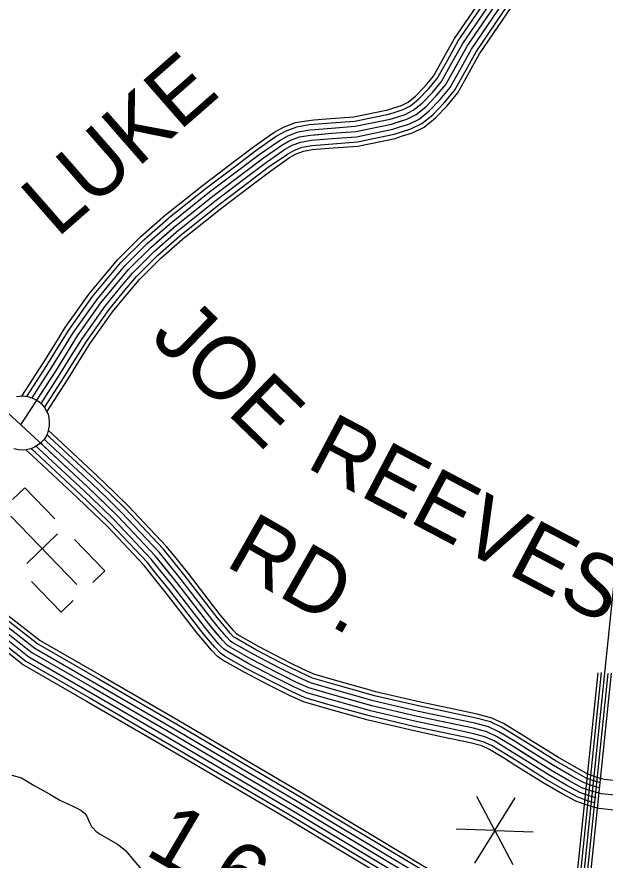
# Model space of a CAD drawing. Extents: x 1551132 to 1791609, y 378168 to 563823.
# Drawn here: x 1703654 to 1707137, y 427562 to 432556 of the extents above; entities that cross this region are included whole.
import ezdxf

# ---------------------------------------------------------------- set-up
doc = ezdxf.new("R2010")
doc.units = 0
for name, color, linetype in [('DESIGN - ROW - Right-of-Way and Easement Labels', 7, 'Continuous'), ('DESIGN - TRAFFIC CONTROL PERMANENT - Signalization', 7, 'Continuous'), ('DESIGN - TRANSPORTATION - Text', 7, 'Continuous'), ('DESIGN - UTILITIES - Cable (Underground) with Text', 7, 'Continuous'), ('SURVEY - CENTERLINE - Preliminary Text', 7, 'Continuous'), ('SURVEY - DRAINAGE - Natural Features', 7, 'Continuous'), ('SURVEY - TRANSPORTATION - Roads', 7, 'Continuous'), ('SURVEY - VEGETATION - Features with Text', 7, 'Continuous')]:
    doc.layers.add(name, color=color, linetype=linetype)

msp = doc.modelspace()

# ---------------------------------------------------------------- linework, layer by layer
at = {"layer": 'DESIGN - TRAFFIC CONTROL PERMANENT - Signalization'}
for q in [(1706376.357, 427939.716), (1706604.323, 427931.755), (1706255.495, 427746.288), (1706362.55, 427544.899), (1706590.517, 427536.946), (1706711.378, 427730.366)]:
    msp.add_line((1706483.462, 427738.327), q, dxfattribs=at)
at = {"layer": 'DESIGN - TRANSPORTATION - Text'}
msp.add_lwpolyline([(1703623.646, 428065.801), (1703681.469, 428049.1), (1703756.984, 428004.149), (1703848.424, 427953.006), (1703908.022, 427916.264), (1703985.645, 427881.305), (1704029.419, 427860.762), (1704041.327, 427852.612), (1704057.177, 427838.403), (1704068.993, 427822.245), (1704084.568, 427784.019), (1704096.326, 427761.851), (1704104.234, 427753.751), (1704122.017, 427733.517), (1704143.833, 427717.242), (1704199.499, 427686.541), (1704249.164, 427655.924), (1704274.963, 427637.598), (1704298.746, 427617.289), (1704344.145, 427562.688), (1704419.185, 427475.702)], dxfattribs=at)
at = {"layer": 'DESIGN - UTILITIES - Cable (Underground) with Text'}
for p, q in [((1703700.78, 429767.058), (1703629.062, 429697.797)), ((1703879.036, 429582.255), (1703700.697, 429767.016)), ((1703894.738, 429494.028), (1703712.268, 429317.805)), ((1704175.338, 429275.567), (1703995.99, 429461.162)), ((1704175.205, 429275.484), (1704103.662, 429206.306)), ((1703741.578, 429211.72), (1703916.351, 429030.834)), ((1703916.443, 429030.967), (1703987.144, 429099.211))]:
    msp.add_line(p, q, dxfattribs=at)
msp.add_lwpolyline([(1703618.588, 429599.503), (1704009.76, 429194.514)], dxfattribs=at)
at = {"layer": 'SURVEY - CENTERLINE - Preliminary Text'}
for points in [[(1701209.763, 432652.228), (1701359.142, 432553.751), (1701538.755, 432418.539), (1701759.974, 432215.675), (1701910.154, 432034.471), (1702098.975, 431751.98), (1702303.228, 431418.996), (1702465.316, 431131.347), (1702571.305, 430911.817), (1702659.186, 430687.844), (1702742.334, 430398.612), (1702844.765, 430049.611), (1702965.145, 429690.66), (1703047.685, 429445.92), (1703104.967, 429331.659), (1703251.713, 429128.287), (1703332.061, 429031.801), (1703487.766, 428880.23), (1703693.511, 428717.901), (1704065.744, 428504.096), (1704501.958, 428251.081), (1705242.932, 427815.937), (1705944.374, 427394.851), (1706600.392, 427005.216)], [(1701445.449, 432676.179), (1701634.594, 432533.792), (1701868.705, 432319.103), (1702030.343, 432124.082), (1702225.063, 431832.757), (1702432.292, 431494.924), (1702598.071, 431200.716), (1702708.602, 430971.802), (1702801.124, 430735.979), (1702886.106, 430440.379), (1702987.611, 430094.512), (1703107.05, 429738.394), (1703186.206, 429503.68), (1703233.414, 429409.519), (1703370.077, 429220.106), (1703442.092, 429133.629), (1703586.613, 428992.95), (1703777.609, 428842.255), (1704140.584, 428633.766), (1704577.423, 428380.393), (1705319.364, 427944.673), (1706021.122, 427523.404), (1706676.84, 427133.944)], [(1701459.698, 432696.388), (1701650.41, 432552.818), (1701886.663, 432336.179), (1702050.184, 432138.874), (1702245.88, 431846.091), (1702453.599, 431507.457), (1702619.995, 431212.166), (1702731.268, 430981.702), (1702824.557, 430743.921), (1702909.838, 430447.271), (1703011.194, 430101.929), (1703130.474, 429746.27), (1703209.073, 429513.214), (1703254.621, 429422.37), (1703389.618, 429235.265), (1703460.258, 429150.438), (1703602.93, 429011.559), (1703791.492, 428862.788), (1704152.942, 428655.175), (1704589.881, 428401.735), (1705331.989, 427965.932), (1706033.797, 427544.63), (1706689.465, 427155.195)], [(1701409.708, 432625.478), (1701594.903, 432486.066), (1701823.681, 432276.269), (1701980.569, 432086.972), (1702172.848, 431799.306), (1702378.843, 431463.481), (1702543.097, 431171.99), (1702651.745, 430946.959), (1702742.342, 430716.045), (1702826.565, 430423.079), (1702928.454, 430075.92), (1703048.285, 429718.627), (1703128.841, 429479.763), (1703180.223, 429377.277), (1703321.061, 429182.08), (1703396.526, 429091.461), (1703545.681, 428946.274), (1703742.785, 428790.762), (1704109.593, 428580.065), (1704546.174, 428326.841), (1705287.715, 427891.364), (1705989.34, 427470.17), (1706645.183, 427080.635)], [(1701409.708, 432625.478), (1701594.903, 432486.066), (1701823.681, 432276.269), (1701980.569, 432086.972), (1702172.848, 431799.306), (1702378.843, 431463.481), (1702543.097, 431171.99), (1702651.745, 430946.959), (1702742.342, 430716.045), (1702826.565, 430423.079), (1702928.454, 430075.92), (1703048.285, 429718.627), (1703128.841, 429479.763), (1703180.223, 429377.277), (1703321.061, 429182.08), (1703396.526, 429091.461), (1703545.681, 428946.274), (1703742.785, 428790.762), (1704109.593, 428580.065), (1704546.174, 428326.841), (1705287.715, 427891.364), (1705989.34, 427470.17), (1706645.183, 427080.635)], [(1701427.574, 432650.828), (1701614.745, 432509.933), (1701846.197, 432297.686), (1702005.452, 432105.523), (1702198.956, 431816.032), (1702405.567, 431479.198), (1702570.588, 431186.357), (1702680.169, 430959.376), (1702771.733, 430726.012), (1702856.331, 430431.729), (1702958.029, 430085.22), (1703077.667, 429728.511), (1703157.524, 429491.721), (1703206.823, 429393.394), (1703345.569, 429201.089), (1703419.309, 429112.545), (1703566.147, 428969.616), (1703760.201, 428816.512), (1704125.092, 428606.915), (1704561.799, 428353.617), (1705303.539, 427918.023), (1706005.231, 427496.787), (1706661.016, 427107.285)], [(1701373.967, 432574.776), (1701555.213, 432438.34), (1701778.657, 432233.434), (1701930.795, 432049.863), (1702120.632, 431765.856), (1702325.394, 431432.039), (1702488.124, 431143.264), (1702594.888, 430922.117), (1702683.56, 430696.111), (1702767.025, 430405.778), (1702869.297, 430057.328), (1702989.519, 429698.86), (1703071.476, 429455.845), (1703127.033, 429345.034), (1703272.046, 429144.054), (1703350.961, 429049.293), (1703504.749, 428899.598), (1703707.961, 428739.269), (1704078.602, 428526.363), (1704514.925, 428273.29), (1705256.065, 427838.054), (1705957.557, 427416.935), (1706613.525, 427027.325)], [(1701391.842, 432600.127), (1701575.062, 432462.199), (1701801.165, 432254.852), (1701955.686, 432068.422), (1702146.74, 431782.581), (1702352.119, 431447.764), (1702515.606, 431157.623), (1702623.32, 430934.542), (1702712.951, 430706.078), (1702796.799, 430414.429), (1702898.88, 430066.62), (1703018.902, 429708.744), (1703100.158, 429467.804), (1703153.624, 429361.16), (1703296.554, 429163.071), (1703373.743, 429070.377), (1703525.215, 428922.932), (1703725.368, 428765.011), (1704094.093, 428553.214), (1704530.549, 428300.066), (1705271.89, 427864.705), (1705973.448, 427443.552), (1706629.35, 427053.984)]]:
    msp.add_lwpolyline(points, dxfattribs=at)
at = {"layer": 'SURVEY - DRAINAGE - Natural Features'}
for points in [[(1706251.033, 425895.095), (1706290.29, 426025.382), (1706314.398, 426110.784), (1706268.483, 426269.955), (1706539.46, 426249.146), (1706671.282, 427285.932), (1706990.5, 427277.907), (1707208.862, 429376.628), (1707434.457, 429376.962), (1707947.338, 433586.489)], [(1706251.033, 425895.095), (1706290.29, 426025.382), (1706314.398, 426110.784), (1706268.483, 426269.955), (1706539.46, 426249.146), (1706671.282, 427285.932), (1706990.5, 427277.907), (1707208.862, 429376.628), (1707434.457, 429376.962), (1707947.338, 433586.489)], [(1706954.542, 427318.824), (1707095.231, 428671.027)], [(1706972.517, 427298.366), (1707115.522, 428672.802)], [(1706990.5, 427277.907), (1707135.305, 428669.685)], [(1707008.474, 427257.464), (1707155.08, 428666.485)], [(1707025.557, 427238.006), (1707174.471, 428669.235)]]:
    msp.add_lwpolyline(points, dxfattribs=at)
at = {"layer": 'SURVEY - TRANSPORTATION - Roads'}
for points in [[(1706182.354, 432314.622), (1706245.303, 432427.608), (1706436.032, 432708.432), (1706457.048, 432740.1)], [(1706204.82, 432302.105), (1706267.219, 432414.099), (1706457.381, 432694.098), (1706478.472, 432725.883)], [(1706231.895, 432287.021), (1706293.627, 432397.816), (1706483.114, 432676.823), (1706504.297, 432708.741)], [(1703678.062, 430138.93), (1703883.84, 430458.214), (1704013.954, 430666.853), (1704151.909, 430861.391), (1704315.881, 431059.638), (1704447.153, 431190.216), (1704598.424, 431322.57), (1704814.052, 431494.208), (1705106.129, 431715.006), (1705222.876, 431795.716), (1705271.125, 431823.183), (1705327.299, 431844.551), (1705393.347, 431855.801), (1705519.328, 431866.368), (1705661.291, 431876.752), (1705871.536, 431920.378), (1705963.751, 431949.345), (1706017.991, 431976.738), (1706074.423, 432022.122), (1706137.063, 432087.441), (1706193.729, 432154.834), (1706320.043, 432381.532), (1706508.855, 432659.539)], [(1706258.977, 432271.929), (1706320.043, 432381.532), (1706508.855, 432659.539), (1706530.129, 432691.598)], [(1706286.06, 432256.837), (1706346.459, 432365.248), (1706534.596, 432642.255), (1706555.962, 432674.456)], [(1706313.134, 432241.753), (1706372.866, 432348.964), (1706560.329, 432624.98), (1706581.787, 432657.314)], [(1706334.726, 432229.72), (1706393.924, 432335.981), (1706580.853, 432611.205), (1706602.378, 432643.647)], [(1705885.753, 432016.789), (1705930.618, 432030.881), (1705970.217, 432050.881), (1706015.041, 432086.932), (1706071.773, 432146.092), (1706121.189, 432204.86), (1706182.362, 432314.647)], [(1705893.461, 431992.255), (1705940.335, 432006.98), (1705984.217, 432029.139), (1706032.449, 432067.932), (1706090.915, 432128.892), (1706142.455, 432190.193), (1706204.829, 432302.13)], [(1705902.744, 431962.679), (1705952.043, 431978.163), (1706001.108, 432002.938), (1706053.432, 432045.023), (1706113.989, 432108.166), (1706168.096, 432172.518), (1706231.903, 432287.038)], [(1705912.035, 431933.103), (1705963.751, 431949.345), (1706017.991, 431976.738), (1706074.423, 432022.122), (1706137.063, 432087.441), (1706193.729, 432154.834), (1706258.986, 432271.946)], [(1705921.327, 431903.527), (1705975.459, 431920.528), (1706034.874, 431950.537), (1706095.414, 431999.222), (1706160.138, 432066.715), (1706219.362, 432137.15), (1706286.068, 432256.854)], [(1705930.61, 431873.952), (1705987.167, 431891.711), (1706051.765, 431924.336), (1706116.397, 431976.313), (1706183.212, 432045.99), (1706245.003, 432119.475), (1706313.143, 432241.762)], [(1705938.018, 431850.368), (1705996.5, 431868.735), (1706065.223, 431903.444), (1706133.13, 431958.054), (1706201.612, 432029.464), (1706265.435, 432105.375), (1706334.734, 432229.736)], [(1705411.889, 431945.378), (1705512.461, 431953.82), (1705649.133, 431963.812), (1705849.428, 432005.38), (1705885.769, 432016.789)], [(1705414.039, 431919.753), (1705514.478, 431928.178), (1705652.691, 431938.287), (1705855.912, 431980.454), (1705893.477, 431992.255)], [(1705416.63, 431888.86), (1705516.903, 431897.277), (1705656.991, 431907.519), (1705863.72, 431950.42), (1705902.761, 431962.679)], [(1704934.016, 431694.855), (1705054.722, 431786.107), (1705176.153, 431870.051), (1705233.618, 431902.769), (1705304.125, 431929.586), (1705382.289, 431942.903), (1705411.897, 431945.387)], [(1704949.524, 431674.338), (1705069.788, 431765.257), (1705189.852, 431848.259), (1705244.609, 431879.435), (1705310.916, 431904.652), (1705385.531, 431917.361), (1705414.047, 431919.761)], [(1705419.222, 431857.968), (1705519.328, 431866.368), (1705661.291, 431876.752), (1705871.536, 431920.378), (1705912.052, 431933.103)], [(1705421.813, 431827.075), (1705521.753, 431835.459), (1705665.591, 431845.984), (1705879.353, 431890.335), (1705921.343, 431903.527)], [(1704968.216, 431649.612), (1705087.963, 431740.131), (1705206.36, 431821.983), (1705257.867, 431851.309), (1705319.107, 431874.601), (1705389.439, 431886.585), (1705416.647, 431888.869)], [(1704986.907, 431624.878), (1705106.129, 431715.006), (1705222.876, 431795.716), (1705271.125, 431823.183), (1705327.299, 431844.551), (1705393.347, 431855.801), (1705419.238, 431857.976)], [(1705424.405, 431796.183), (1705524.178, 431804.558), (1705669.891, 431815.217), (1705887.161, 431860.301), (1705930.626, 431873.952)], [(1705005.598, 431600.144), (1705124.295, 431689.88), (1705239.393, 431769.449), (1705284.383, 431795.058), (1705335.49, 431814.5), (1705397.256, 431825.017), (1705421.83, 431827.084)], [(1705426.472, 431771.549), (1705526.119, 431779.916), (1705673.316, 431790.683), (1705893.394, 431836.351), (1705938.035, 431850.368)], [(1705024.289, 431575.418), (1705142.47, 431664.754), (1705255.901, 431743.173), (1705297.641, 431766.932), (1705343.682, 431784.449), (1705401.164, 431794.241), (1705424.43, 431796.191)], [(1705039.197, 431555.701), (1705156.953, 431644.72), (1705269.067, 431722.231), (1705308.208, 431744.506), (1705350.207, 431760.482), (1705404.28, 431769.699), (1705426.497, 431771.565)], [(1704534.876, 431383.522), (1704542.2, 431389.93), (1704760.287, 431563.526), (1704934.025, 431694.863)], [(1704551.809, 431364.171), (1704558.683, 431370.18), (1704776.045, 431543.201), (1704949.533, 431674.346)], [(1704572.225, 431340.837), (1704578.558, 431346.379), (1704795.053, 431518.709), (1704968.224, 431649.62)], [(1704592.633, 431317.503), (1704598.424, 431322.57), (1704814.052, 431494.208), (1704986.915, 431624.886)], [(1704613.04, 431294.169), (1704618.29, 431298.761), (1704833.052, 431469.707), (1705005.606, 431600.152)], [(1704633.457, 431270.835), (1704638.165, 431274.96), (1704852.06, 431445.215), (1705024.298, 431575.427)], [(1704649.731, 431252.235), (1704654.006, 431255.977), (1704867.21, 431425.681), (1705039.206, 431555.71)], [(1704170.834, 431021.904), (1704251.007, 431118.831), (1704387.287, 431254.385), (1704534.884, 431383.53)], [(1704190.65, 431005.512), (1704270.023, 431101.472), (1704404.837, 431235.576), (1704551.817, 431364.171)], [(1704214.541, 430985.753), (1704292.956, 431080.555), (1704425.995, 431212.892), (1704572.233, 431340.845)], [(1704238.424, 430965.994), (1704315.881, 431059.638), (1704447.153, 431190.216), (1704592.641, 431317.512)], [(1704262.307, 430946.235), (1704338.805, 431038.721), (1704468.31, 431167.541), (1704613.049, 431294.178)], [(1704286.198, 430926.476), (1704361.738, 431017.804), (1704489.468, 431144.857), (1704633.465, 431270.852)], [(1704305.239, 430910.717), (1704380.012, 431001.12), (1704506.335, 431126.773), (1704649.74, 431252.243)], [(1703872.982, 430606.568), (1703940.906, 430715.479), (1704082.244, 430914.792), (1704170.842, 431021.912)], [(1703894.799, 430592.959), (1703962.322, 430701.22), (1704102.669, 430899.134), (1704190.659, 431005.52)], [(1703921.106, 430576.558), (1703988.138, 430684.036), (1704127.285, 430880.267), (1704214.541, 430985.761)], [(1703947.406, 430560.15), (1704013.954, 430666.853), (1704151.909, 430861.391), (1704238.432, 430966.002)], [(1703973.705, 430543.741), (1704039.77, 430649.669), (1704176.534, 430842.516), (1704262.324, 430946.243)], [(1704000.013, 430527.341), (1704065.586, 430632.485), (1704201.15, 430823.648), (1704286.206, 430926.484)], [(1704020.979, 430514.257), (1704086.169, 430618.785), (1704220.783, 430808.598), (1704305.256, 430910.734)], [(1707254.994, 427940.158), (1707115.289, 427953.766), (1707057.532, 427970.433), (1706999.816, 427991.109), (1706924.335, 428031.993), (1706815.137, 428095.278), (1706586.926, 428237.973), (1706493.645, 428295.075), (1706435.996, 428321.75), (1706358.307, 428342.651), (1706025.414, 428412.503), (1705756.387, 428475.613), (1705525.334, 428540.289), (1705381.938, 428581.957), (1705306.39, 428616.841), (1705189.142, 428674.218), (1705042.138, 428751.944), (1704917.041, 428823.413), (1704899.191, 428835.63), (1704871.533, 428863.964), (1704790.669, 428960.942), (1704601.515, 429205.256), (1704473.376, 429364.81), (1704252.148, 429599.483), (1704074.202, 429771.621), (1703757.718, 430065.42), (1703099.001, 430673.311)], [(1703683.637, 430309.493), (1703809.759, 430505.19), (1703872.991, 430606.576)], [(1703713.244, 430307.968), (1703831.475, 430491.415), (1703894.807, 430592.967)], [(1703744.519, 430299.259), (1703857.658, 430474.814), (1703921.115, 430576.567)], [(1703772.235, 430285.042), (1703883.84, 430458.214), (1703947.414, 430560.158)], [(1703797.326, 430266.759), (1703910.023, 430441.613), (1703973.713, 430543.749)], [(1703818.525, 430242.416), (1703936.206, 430425.013), (1704000.021, 430527.349)], [(1703831.65, 430217.166), (1703957.08, 430411.779), (1704020.996, 430514.265)], [(1703865.082, 430084.071), (1703840.433, 430106.946)], [(1703848.266, 430065.962), (1703832.125, 430080.945)], [(1704213.724, 429722.92), (1704116.851, 429816.63), (1703848.258, 430065.97)], [(1704230.907, 429740.678), (1704133.851, 429834.572), (1703865.074, 430084.087)], [(1703784.993, 429997.802), (1703767.685, 430013.869)], [(1703806.084, 430020.519), (1703794.342, 430031.419)], [(1704170.617, 429678.352), (1704074.202, 429771.621), (1703806.075, 430020.527)], [(1703827.175, 430043.236), (1703815.634, 430053.953)], [(1704192.166, 429700.636), (1704095.527, 429794.121), (1703827.167, 430043.244)], [(1703746.41, 429956.234), (1703709.328, 429990.66)], [(1703763.901, 429975.076), (1703739.202, 429998.002)], [(1704109.635, 429615.3), (1704013.862, 429707.944), (1703746.402, 429956.234)], [(1704127.509, 429633.784), (1704031.553, 429726.611), (1703763.893, 429975.084)], [(1704149.067, 429656.068), (1704052.878, 429749.12), (1703784.984, 429997.81)], [(1704561.816, 429353.702), (1704520.175, 429405.553), (1704296.28, 429643.051), (1704213.716, 429722.928)], [(1704581.09, 429369.177), (1704538.833, 429421.795), (1704313.872, 429660.426), (1704230.899, 429740.687)], [(1704489.309, 429295.467), (1704449.977, 429344.443), (1704230.082, 429577.699), (1704149.059, 429656.076)], [(1704513.475, 429314.876), (1704473.376, 429364.81), (1704252.148, 429599.483), (1704170.608, 429678.36)], [(1704537.641, 429334.285), (1704496.776, 429385.178), (1704274.214, 429621.267), (1704192.158, 429700.644)], [(1704445.085, 429259.949), (1704407.161, 429307.167), (1704189.708, 429537.84), (1704109.626, 429615.308)], [(1704465.135, 429276.05), (1704426.577, 429324.068), (1704208.016, 429555.915), (1704127.501, 429633.792)], [(1704889.55, 428977.759), (1704858.275, 429015.276), (1704669.605, 429258.958), (1704581.074, 429369.194)], [(1704822.951, 428922.224), (1704790.669, 428960.942), (1704601.515, 429205.256), (1704513.467, 429314.892)], [(1704846.759, 428942.074), (1704814.835, 428980.367), (1704625.856, 429224.457), (1704537.633, 429334.301)], [(1704870.567, 428961.933), (1704839.001, 428999.784), (1704650.197, 429243.649), (1704561.807, 429353.718)], [(1704755.586, 428866.047), (1704722.287, 428905.982), (1704532.633, 429150.938), (1704445.077, 429259.966)], [(1704775.336, 428882.514), (1704742.336, 428922.099), (1704552.833, 429166.863), (1704465.126, 429276.066)], [(1704799.143, 428902.373), (1704766.502, 428941.516), (1704577.174, 429186.056), (1704489.301, 429295.483)], [(1705263.574, 428706.818), (1705217.267, 428729.486), (1705072.012, 428806.279), (1704949.981, 428875.998), (1704939.273, 428883.331), (1704917.599, 428905.54), (1704870.558, 428961.95)], [(1705274.44, 428729.019), (1705228.475, 428751.511), (1705083.92, 428827.946), (1704963.114, 428896.965), (1704955.248, 428902.348), (1704935.957, 428922.107), (1704889.541, 428977.775)], [(1705236.325, 428651.125), (1705189.142, 428674.218), (1705042.138, 428751.944), (1704917.041, 428823.413), (1704899.191, 428835.63), (1704871.533, 428863.964), (1704822.943, 428922.241)], [(1705249.949, 428678.968), (1705203.2, 428701.852), (1705057.071, 428779.112), (1704933.507, 428849.705), (1704919.232, 428859.481), (1704894.566, 428884.748), (1704846.751, 428942.091)], [(1705197.767, 428572.34), (1705149.352, 428596.032), (1704999.872, 428675.067), (1704870.442, 428749.011), (1704842.484, 428768.145), (1704806.368, 428805.146), (1704755.578, 428866.064)], [(1705209.075, 428595.432), (1705161.018, 428618.949), (1705012.263, 428697.61), (1704884.1, 428770.828), (1704859.109, 428787.929), (1704825.468, 428822.388), (1704775.327, 428882.531)], [(1705222.7, 428623.283), (1705175.084, 428646.583), (1705027.205, 428724.777), (1704900.574, 428797.121), (1704879.15, 428811.779), (1704848.5, 428843.18), (1704799.135, 428902.39)], [(1705724.463, 428548.939), (1705542.342, 428599.916), (1705403.704, 428640.2), (1705333.014, 428672.843), (1705263.566, 428706.827)], [(1705731.13, 428572.74), (1705549.117, 428623.683), (1705412.379, 428663.417), (1705343.63, 428695.16), (1705274.432, 428729.027)], [(1705716.113, 428519.08), (1705533.834, 428570.098), (1705392.821, 428611.074), (1705319.698, 428644.842), (1705249.941, 428678.976)], [(1705699.397, 428459.379), (1705516.835, 428510.48), (1705371.055, 428552.839), (1705293.082, 428588.84), (1705222.692, 428623.291)], [(1705707.755, 428489.23), (1705525.334, 428540.289), (1705381.938, 428581.957), (1705306.39, 428616.841), (1705236.316, 428651.134)], [(1705684.114, 428404.761), (1705501.277, 428455.937), (1705351.147, 428499.555), (1705268.724, 428537.614), (1705197.759, 428572.34)], [(1705691.047, 428429.52), (1705508.327, 428480.663), (1705360.172, 428523.714), (1705279.765, 428560.84), (1705209.067, 428595.44)], [(1706212.677, 428461.812), (1706044.222, 428497.163), (1705777.987, 428559.615), (1705731.113, 428572.74)], [(1706201.235, 428407.286), (1706032.139, 428442.77), (1705764.112, 428505.647), (1705716.097, 428519.08)], [(1706207.602, 428437.62), (1706038.864, 428473.029), (1705771.829, 428535.672), (1705724.446, 428548.939)], [(1706188.502, 428346.601), (1706018.69, 428382.235), (1705748.663, 428445.578), (1705699.38, 428459.379)], [(1706194.869, 428376.943), (1706025.414, 428412.503), (1705756.387, 428475.613), (1705707.739, 428489.23)], [(1706700.415, 428269.283), (1706632.55, 428311.717), (1706534.627, 428371.66), (1706465.679, 428403.569), (1706378.489, 428427.02), (1706212.66, 428461.821)], [(1706182.136, 428316.267), (1706011.965, 428351.976), (1705740.946, 428415.553), (1705691.031, 428429.52)], [(1706670.874, 428222.04), (1706603.234, 428264.341), (1706508.295, 428322.451), (1706446.604, 428351.001), (1706365.523, 428372.81), (1706201.219, 428407.294)], [(1706687.307, 428248.324), (1706619.542, 428290.7), (1706522.944, 428349.835), (1706457.221, 428380.244), (1706372.74, 428402.978), (1706207.585, 428437.628)], [(1706176.852, 428291.091), (1706006.39, 428326.867), (1705734.538, 428390.635), (1705684.097, 428404.761)], [(1706654.441, 428195.756), (1706586.926, 428237.973), (1706493.645, 428295.075), (1706435.996, 428321.75), (1706358.307, 428342.651), (1706194.852, 428376.952)], [(1706621.575, 428143.188), (1706554.31, 428185.247), (1706464.346, 428240.315), (1706414.772, 428263.257), (1706343.874, 428282.324), (1706182.119, 428316.275)], [(1706638.008, 428169.472), (1706570.618, 428211.606), (1706478.995, 428267.699), (1706425.388, 428292.5), (1706351.09, 428312.492), (1706188.486, 428346.609)], [(1706607.934, 428121.379), (1706540.777, 428163.38), (1706452.196, 428217.606), (1706405.972, 428238.99), (1706337.89, 428257.307), (1706176.836, 428291.1)], [(1707117.214, 428043.468), (1707084.198, 428052.994), (1707035.291, 428070.511), (1706966.734, 428107.653), (1706859.878, 428169.58), (1706700.407, 428269.291)], [(1707101.764, 427989.934), (1707067.065, 427999.951), (1707012.499, 428019.493), (1706939.493, 428059.035), (1706831.129, 428121.837), (1706670.866, 428222.048)], [(1707110.355, 428019.718), (1707076.598, 428029.46), (1707025.182, 428047.885), (1706954.651, 428086.086), (1706847.12, 428148.404), (1706687.299, 428248.332)], [(1707084.581, 427930.366), (1707047.999, 427940.916), (1706987.133, 427962.725), (1706909.177, 428004.951), (1706799.146, 428068.719), (1706638, 428169.48)], [(1707093.172, 427960.15), (1707057.532, 427970.433), (1706999.816, 427991.109), (1706924.335, 428031.993), (1706815.137, 428095.278), (1706654.433, 428195.764)], [(1707068.856, 427875.872), (1707030.557, 427886.923), (1706963.934, 427910.79), (1706881.452, 427955.466), (1706769.88, 428020.118), (1706607.934, 428121.387)], [(1707075.99, 427900.581), (1707038.465, 427911.407), (1706974.45, 427934.332), (1706894.019, 427977.9), (1706783.155, 428042.152), (1706621.567, 428143.196)], [(1707611.752, 427949.866), (1707497.238, 427991.609), (1707421.056, 428005.593), (1707375.883, 428014.743), (1707263.694, 428026.443), (1707131.647, 428039.302), (1707117.189, 428043.468)], [(1707552.012, 427785.979), (1707451.306, 427822.688), (1707387.991, 427834.305), (1707349.458, 427842.113), (1707246.194, 427852.88), (1707098.747, 427867.247), (1707068.848, 427875.864)]]:
    msp.add_lwpolyline(points, dxfattribs=at)
at = {"layer": 'SURVEY - VEGETATION - Features with Text'}
msp.add_lwpolyline([(1703651.471, 430307.335), (1703673.837, 430309.985), (1703691.787, 430310.685), (1703718.744, 430307.451), (1703737.277, 430302.185), (1703752.06, 430295.768), (1703769.36, 430286.884), (1703783.401, 430277.851), (1703798.167, 430265.8), (1703811.567, 430251.067), (1703821.767, 430235.524), (1703830.075, 430218.941), (1703838.433, 430202.315), (1703843.6, 430181.223), (1703846.166, 430153.789), (1703845.491, 430134.614), (1703842.325, 430113.33), (1703835.208, 430090.904), (1703828.267, 430071.204), (1703814.867, 430053.178), (1703798.784, 430035.119), (1703780.293, 430021.186), (1703757.785, 430007.052), (1703737.302, 429997.993), (1703717.536, 429992.96), (1703696.253, 429989.785), (1703663.679, 429991.143), (1703635.388, 429998.068)], dxfattribs=at)

# ---------------------------------------------------------------- texts
at = {"layer": 'DESIGN - ROW - Right-of-Way and Easement Labels'}
for s, height, rotation, p in [('LUKE', 369.9995, 41.185506, (1703892.199, 431242.409)), ('JOE', 370, 315.952058, (1704436.336, 430649.502)), ('REEVES', 369.9952, 332.131775, (1705358.631, 429892.175)), ('RD.', 369.9957, 330.259867, (1704879.458, 429309.859))]:
    msp.add_text(s, height=height, rotation=rotation, dxfattribs=at).set_placement(p)
at = {"layer": 'DESIGN - TRAFFIC CONTROL PERMANENT - Signalization'}
msp.add_text('1.6', height=369.9959, rotation=329.575989, dxfattribs=at).set_placement((1704404.076, 427600.755))

doc.saveas('drawing.dxf')
